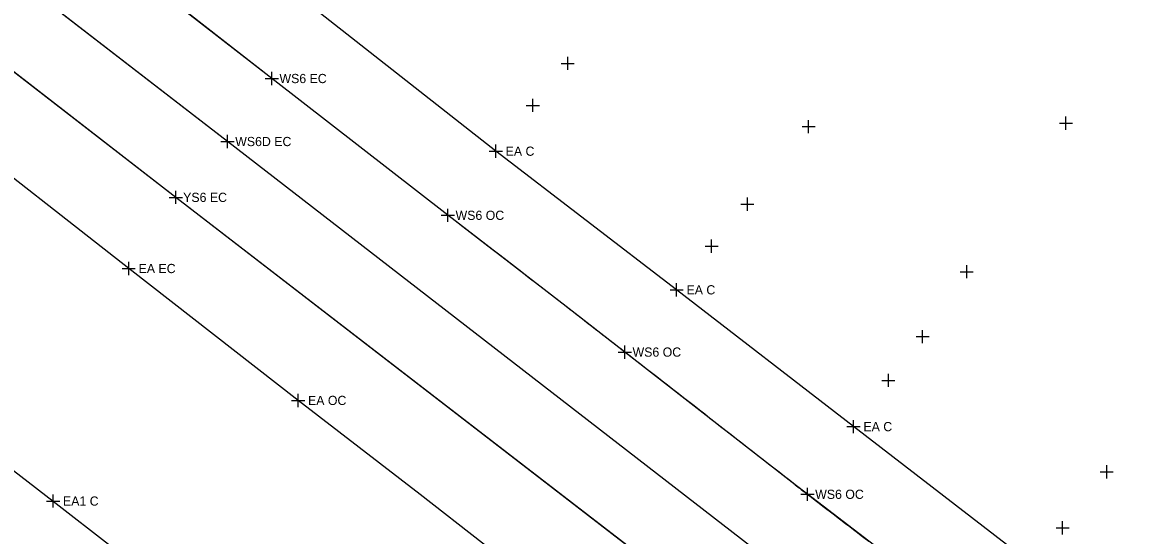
# Model space of a CAD drawing. Extents: x 1324236 to 1326110, y 459090 to 460782.
# Drawn here: x 1324868.3 to 1325040, y 460225.9 to 460303.9 of the extents above; entities that cross this region are included whole.
import ezdxf

# ---------------------------------------------------------------- set-up
doc = ezdxf.new("R2010")
doc.units = 0
for name, color, linetype in [('BD_X_Canopy', 7, 'Continuous'), ('DR_X_Ditch', 7, 'Continuous'), ('DV_X_Property_Line', 7, 'Continuous'), ('PM_X_Edge_Line', 7, 'Continuous'), ('PM_X_Lane_Line', 7, 'Continuous'), ('PV_X_Shoulder', 7, 'Continuous'), ('RW_X_CL', 7, 'Continuous')]:
    doc.layers.add(name, color=color, linetype=linetype)

msp = doc.modelspace()

# ---------------------------------------------------------------- linework, layer by layer
at = {"layer": 'BD_X_Canopy'}
msp.add_lwpolyline([(1325040.71, 460177.13), (1325034.15, 460182.03), (1325034.15, 460182.03), (1325034.11, 460182.06), (1325034.11, 460182.06), (1325008.87, 460201.31), (1324998.99, 460208.86), (1324998.99, 460208.86), (1324980.52, 460223.01), (1324980.52, 460223.01), (1324899.46, 460285.8), (1324816.32, 460350.02)], dxfattribs=at)
at = {"layer": 'DR_X_Ditch'}
for points in [[(1325055.08, 460152.45), (1325039.72, 460163.87), (1325039.72, 460163.87), (1325028.27, 460172.43), (1325028.27, 460172.43), (1325025.54, 460174.5), (1325025.54, 460174.5), (1325000.85, 460193.34), (1325000.85, 460193.34), (1324991.73, 460200.28), (1324991.73, 460200.28), (1324973.58, 460214.01), (1324973.58, 460214.01), (1324891.6, 460277.31), (1324809.63, 460340.84)], [(1325042.01, 460190.54), (1325032.41, 460197.89), (1325032.41, 460197.89), (1325015.3, 460211), (1325015.3, 460211), (1324996.92, 460225.02), (1324996.92, 460225.02), (1324987.58, 460232.16), (1324987.58, 460232.16), (1324985.69, 460233.62), (1324985.69, 460233.62), (1324959.83, 460253.78), (1324959.83, 460253.78), (1324950.92, 460260.7), (1324950.92, 460260.7), (1324932.94, 460274.58), (1324932.94, 460274.58), (1324906.18, 460295.38), (1324878.81, 460316.8)]]:
    msp.add_lwpolyline(points, dxfattribs=at)
at = {"layer": 'DV_X_Property_Line'}
for p, q in [((1324939.22, 460284.33), (1324941.22, 460284.33)), ((1324940.22, 460283.33), (1324940.22, 460285.33)), ((1324884.45, 460265.49), (1324884.45, 460267.49)), ((1324883.45, 460266.49), (1324885.45, 460266.49)), ((1324966.7, 460263.25), (1324968.7, 460263.25)), ((1324967.7, 460262.25), (1324967.7, 460264.25)), ((1324909.19, 460246.43), (1324911.19, 460246.43)), ((1324910.19, 460245.43), (1324910.19, 460247.43)), ((1324994.58, 460241.45), (1324994.58, 460243.45)), ((1324993.58, 460242.45), (1324995.58, 460242.45)), ((1324871.96, 460231.13), (1324873.96, 460231.13)), ((1324872.96, 460230.13), (1324872.96, 460232.13))]:
    msp.add_line(p, q, dxfattribs=at)
at = {"layer": 'PM_X_Edge_Line'}
for p, q in [((1324891.6, 460277.31), (1324809.63, 460340.84)), ((1324906.18, 460295.38), (1324878.81, 460316.8)), ((1324932.94, 460274.58), (1324906.18, 460295.38)), ((1324973.58, 460214.01), (1324891.6, 460277.31))]:
    msp.add_line(p, q, dxfattribs=at)
for centre, radius, start, end in [((1317335.06, 450413.72), 12448.47, 52.280865, 52.385428), ((1323073.38, 457833.11), 3068.93, 52.07027, 52.28087), ((1288890.23, 413969.89), 58678.91, 52.0382539, 52.0702727), ((1325177.49, 460479.45), 311.8, 232.0383, 232.4775), ((1326660.31, 462410.32), 2746.35, 232.4775, 232.72268)]:
    msp.add_arc(centre, radius, start, end, dxfattribs=at)
at = {"layer": 'PM_X_Lane_Line'}
for p, q in [((1324899.46, 460285.8), (1324816.32, 460350.02)), ((1324980.52, 460223.01), (1324899.46, 460285.8))]:
    msp.add_line(p, q, dxfattribs=at)
at = {"layer": 'PV_X_Shoulder'}
for points in [[(1324669.98, 460389.31), (1324715.86, 460353.85), (1324792.73, 460293.17), (1324872.96, 460231.13), (1324952.76, 460169.1), (1324978.52, 460148.79), (1325005.25, 460128.1), (1325032.05, 460107.12), (1325058.52, 460086.64), (1325084, 460067.05), (1325111.27, 460046.59)], [(1325158.98, 460120.56), (1325156.36, 460117.88), (1325129.2, 460138.06), (1325101.69, 460158.66), (1325088.74, 460168.39), (1325089.9, 460170.12), (1325075.66, 460180.54), (1325048.93, 460200.83), (1325022.04, 460221.26), (1324994.58, 460242.45), (1324967.7, 460263.25), (1324940.22, 460284.33), (1324913.59, 460305.26), (1324886.1, 460326.42), (1324858.75, 460347.83)], [(1325046.51, 460141.66), (1325023.81, 460158.87), (1325023.81, 460158.87), (1325020.3, 460161.53), (1325020.3, 460161.53), (1325013.51, 460166.7), (1325013.51, 460166.7), (1324993.11, 460182.29), (1324993.11, 460182.29), (1324974.5, 460196.54), (1324974.5, 460196.54), (1324964.95, 460203.88), (1324964.95, 460203.88), (1324963.01, 460205.38), (1324963.01, 460205.38), (1324938.22, 460224.74), (1324938.22, 460224.74), (1324928.71, 460232.14), (1324928.71, 460232.14), (1324910.19, 460246.43), (1324910.19, 460246.43), (1324884.45, 460266.49), (1324856.61, 460288.28)]]:
    msp.add_lwpolyline(points, dxfattribs=at)
at = {"layer": 'RW_X_CL'}
for p, q in [((1324950.15, 460297.68), (1324952.15, 460297.68)), ((1324951.15, 460296.68), (1324951.15, 460298.68)), ((1324906.18, 460294.38), (1324906.18, 460296.38)), ((1324905.18, 460295.38), (1324907.18, 460295.38)), ((1324944.84, 460291.29), (1324946.84, 460291.29)), ((1324945.84, 460290.29), (1324945.84, 460292.29)), ((1324987.75, 460287.07), (1324987.75, 460289.07)), ((1325026.85, 460287.6), (1325026.85, 460289.6)), ((1324986.75, 460288.07), (1324988.75, 460288.07)), ((1325025.85, 460288.6), (1325027.85, 460288.6)), ((1324898.46, 460285.8), (1324900.46, 460285.8)), ((1324899.46, 460284.8), (1324899.46, 460286.8)), ((1324890.6, 460277.31), (1324892.6, 460277.31)), ((1324891.6, 460276.31), (1324891.6, 460278.31)), ((1324978.44, 460275.27), (1324978.44, 460277.27)), ((1324932.94, 460273.58), (1324932.94, 460275.58)), ((1324977.44, 460276.27), (1324979.44, 460276.27)), ((1324931.94, 460274.58), (1324933.94, 460274.58)), ((1324973.02, 460268.89), (1324973.02, 460270.89)), ((1324972.02, 460269.89), (1324974.02, 460269.89)), ((1325011.77, 460265), (1325011.77, 460267)), ((1325010.77, 460266), (1325012.77, 460266)), ((1325005.07, 460255.14), (1325005.07, 460257.14)), ((1324959.83, 460252.78), (1324959.83, 460254.78)), ((1325004.07, 460256.14), (1325006.07, 460256.14)), ((1324958.83, 460253.78), (1324960.83, 460253.78)), ((1324998.87, 460249.48), (1325000.87, 460249.48)), ((1324999.87, 460248.48), (1324999.87, 460250.48)), ((1325033.04, 460234.58), (1325033.04, 460236.58)), ((1325032.04, 460235.58), (1325034.04, 460235.58)), ((1324987.58, 460231.16), (1324987.58, 460233.16)), ((1324986.58, 460232.16), (1324988.58, 460232.16)), ((1325026.34, 460226.07), (1325026.34, 460228.07)), ((1325025.34, 460227.07), (1325027.34, 460227.07))]:
    msp.add_line(p, q, dxfattribs=at)

# ---------------------------------------------------------------- texts
at = {"layer": 'DV_X_Property_Line'}
for s, p in [('EA C', (1324941.72, 460283.63)), ('EA EC', (1324885.95, 460265.79)), ('EA C', (1324969.2, 460262.55)), ('EA OC', (1324911.69, 460245.73)), ('EA C', (1324996.08, 460241.75)), ('EA1 C', (1324874.46, 460230.43))]:
    msp.add_text(s, height=1.4, dxfattribs=at).set_placement(p)
at = {"layer": 'RW_X_CL'}
for s, p in [('WS6 EC', (1324907.35, 460294.68)), ('WS6D EC', (1324900.63, 460285.1)), ('YS6 EC', (1324892.72, 460276.61)), ('WS6 OC', (1324934.11, 460273.88)), ('WS6 OC', (1324961, 460253.08)), ('WS6 OC', (1324988.75, 460231.46))]:
    msp.add_text(s, height=1.4, dxfattribs=at).set_placement(p)

doc.saveas('drawing.dxf')
